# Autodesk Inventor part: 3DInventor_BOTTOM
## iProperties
Created: 2006-11
Part Number: 3DInventor_BOTTOM
Document SubType Name: Modeling
Designer: conardl1
Density: 1 g/cm^3
DESCRIPTION: Bottom Part
MODELED_BY: L Conard
Author: conardl1
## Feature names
1. Base1
